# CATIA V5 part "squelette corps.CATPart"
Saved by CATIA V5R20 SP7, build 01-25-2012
Part number: squelette corps vérin gauche
Publications: "Plan.4", "Droite.4"
Bounding box of the stored display mesh (mm): x -17.69 to -7.071, y -54 to -25.951, z 46.916 to 47.6
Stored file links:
  F:\Travaux\Modélisations\CFAO_2011\CFAO_2011_MMS\CFAO_2011_MMS_DONE\CFAO_2011_MMS_jboiteux\Catia\squelette corps.CATPart
  U:\finthinkmotion\stepper.CATProduct
  F:\Travaux\Modélisations\CFAO_2011\CFAO_2011_MMS\CFAO_2011_MMS_DONE\CFAO_2011_MMS_jboiteux\Catia\squelette tige.CATPart
  F:\Travaux\Modélisations\CFAO_2011\CFAO_2011_MMS\CFAO_2011_MMS_DONE\CFAO_2011_MMS_jboiteux\Catia\part4.CATPart
  F:\Travaux\Modélisations\CFAO_2011\CFAO_2011_MMS\CFAO_2011_MMS_DONE\CFAO_2011_MMS_jboiteux\Catia\Part1.CATPart
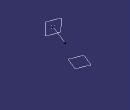
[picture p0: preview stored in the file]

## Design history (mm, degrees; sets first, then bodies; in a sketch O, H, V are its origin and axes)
Set1
  Line1 to Line3: linked copy from another document
Body1 (main body)
  Point1: type OnCurve, Support Line1, Ratio 0
  Line4: type PtDir, RefPoint Point1, Direction Line2, Start 0, End -30
  Plane1: type 2Lines, Element1 Line2, Element2 Line3
  Plane2: type Normal, Curve Line4, RefPoint Point1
